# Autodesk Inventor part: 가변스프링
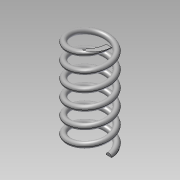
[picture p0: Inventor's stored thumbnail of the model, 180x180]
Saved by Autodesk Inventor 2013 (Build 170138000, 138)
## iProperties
Created: 2020-02
Part Number: 가변스프링
Material: 강철
Document SubType Name: Modeling
Designer: Administrator
Density: 7.85 g/cm^3
Mass: 6.41948 g
Surface Area: 16.6083 cm^2
Volume: 0.817768 cm^3
Author: Administrator
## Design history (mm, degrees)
sketch "스케치1"
  geometry: L1 (0, 0)-(7, 0); L2 (7, 0)-(7, 35.5); L3 (7, 35.5)-(0, 35.5); L4 (0, 35.5)-(0, 0); C1 r 1 at (7, 0)
  constraints: 8 end point, 2 parallel, 1 centre point, 1 coincident, 1 horizontal, 1 perpendicular
  dimensions: "d0" = 2 diameter of C1; "d2" = 14 diameter of L2 L4; "d3" = 35.5 distance of L1.end L2.end (derived)
feature "코일1" sketch "스케치1" pitch "d4" = 10; turns "d6" = 6; dims "d5" = 35.5 (= d3), "d7" = 0, angle "d8" = 90 deg, angle "d9" = 90 deg, "d10" = 0, "d11" = 0
sketch "스케치2"
  geometry: L1 (35.5, -8.5)-(0, -8.5); L2 (0, -8.5)-(0, 8.5); L3 (0, 8.5)-(35.5, 8.5); L4 (35.5, 8.5)-(35.5, -8.5); 2 further points
  constraints: 8 end point, 2 parallel, 1 coincident, 1 horizontal, 1 midpoint, 1 perpendicular
  dimensions: "d12" = 17 distance of L3.end L1.start; "d14" = 35.5 distance of L2.end L3.end (derived)
extrude "돌출1" sketch "스케치2" stored distance "d15" = 17; taper "d16" = 0 deg
node "솔리드1"
